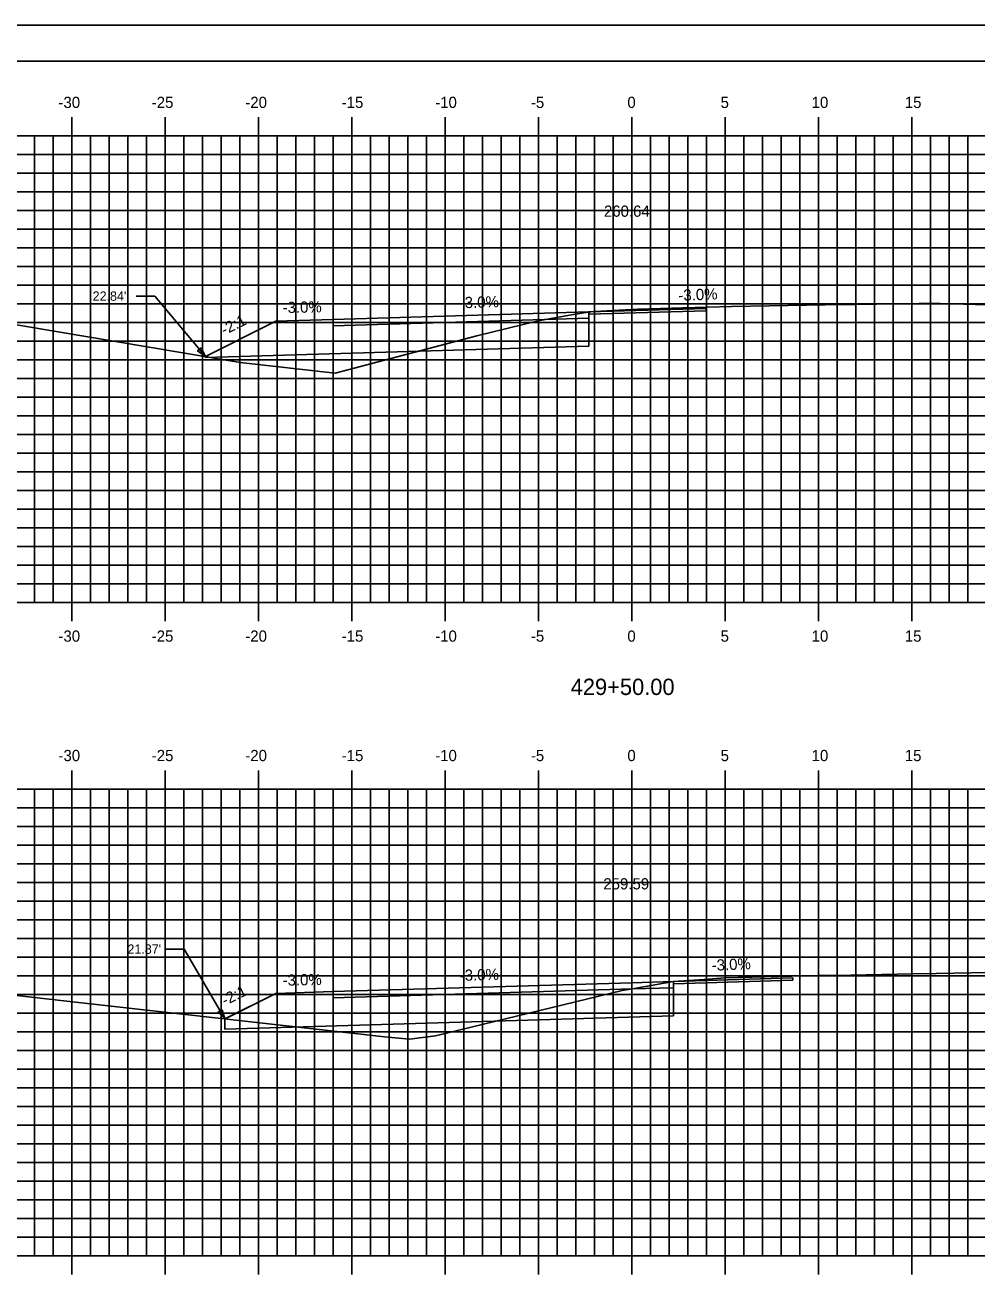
# Model space of a CAD drawing. Extents: x 1160718 to 1173142, y 616002 to 617630.
# Drawn here: x 1171038.7 to 1171089.7, y 616656.7 to 616723.9 of the extents above; entities that cross this region are included whole.
import ezdxf

# ---------------------------------------------------------------- set-up
doc = ezdxf.new("R2010")
doc.units = 0
for name, color, linetype in [('ANNOTATION', 7, 'Continuous'), ('BORDER', 7, 'Continuous'), ('D_Roadway_Centerline', 7, 'Continuous'), ('D_Roadway_Centerline_Text', 7, 'Continuous'), ('D_Roadway_Edge_Shoulder', 7, 'Continuous'), ('D_Roadway_Edge_TW', 7, 'Continuous'), ('D_Roadway_Pavement', 7, 'Continuous'), ('D_Roadway_SlopeLines', 7, 'Continuous'), ('D_Roadway_SubGrade', 7, 'Continuous'), ('H_V ANNOTATION', 7, 'Continuous'), ('MAJOR', 7, 'Continuous'), ('MINOR', 7, 'Continuous'), ('PLOT BOUNDARY', 7, 'Continuous'), ('S_Roadway_Centerline', 7, 'Continuous'), ('SHADING', 7, 'Continuous')]:
    doc.layers.add(name, color=color, linetype=linetype)

msp = doc.modelspace()

# ---------------------------------------------------------------- linework, layer by layer
at = {"layer": 'ANNOTATION'}
for p, q in [((1171044.62, 616709.347), (1171045.62, 616709.347)), ((1171048.335, 616706.106), (1171045.62, 616709.347)), ((1171068.87, 616708.499), (1171075.152, 616708.688)), ((1171068.87, 616708.374), (1171075.152, 616708.563)), ((1171075.152, 616708.688), (1171075.152, 616708.563)), ((1171055.177, 616708.087), (1171052.113, 616707.995)), ((1171046.202, 616674.353), (1171047.202, 616674.353)), ((1171049.37, 616670.612), (1171047.202, 616674.353)), ((1171073.401, 616672.622), (1171079.805, 616672.814)), ((1171079.805, 616672.814), (1171079.805, 616672.689)), ((1171055.177, 616672.075), (1171052.113, 616671.983)), ((1171073.401, 616672.497), (1171079.805, 616672.689))]:
    msp.add_line(p, q, dxfattribs=at)
for points in [[(1171048.11, 616706.57), (1171048.335, 616706.106), (1171047.918, 616706.409)], [(1171049.227, 616671.107), (1171049.37, 616670.612), (1171049.011, 616670.981)]]:
    msp.add_lwpolyline(points, close=True, dxfattribs=at)
at = {"layer": 'BORDER'}
msp.add_line((1171156.177, 616721.928), (1170996.177, 616721.928), dxfattribs=at)
at = {"layer": 'D_Roadway_Centerline'}
for points in [[(1171055.177, 616672.075), (1171071.177, 616672.555), (1171073.401, 616672.622)], [(1171049.421, 616670.637), (1171052.113, 616671.983)]]:
    msp.add_lwpolyline(points, dxfattribs=at)
at = {"layer": 'D_Roadway_Edge_Shoulder'}
for points in [[(1171055.177, 616708.087), (1171055.177, 616707.754)], [(1171055.177, 616672.043), (1171055.177, 616671.71)]]:
    msp.add_lwpolyline(points, dxfattribs=at)
at = {"layer": 'D_Roadway_Edge_TW'}
for points in [[(1171068.875, 616708.165), (1171068.875, 616708.499), (1171068.875, 616708.499), (1171055.177, 616708.087), (1171055.177, 616707.754), (1171068.875, 616708.165)], [(1171073.401, 616672.288), (1171073.401, 616672.622), (1171071.177, 616672.555), (1171055.177, 616672.075), (1171055.177, 616671.742), (1171071.177, 616672.222)]]:
    msp.add_lwpolyline(points, close=True, dxfattribs=at)
at = {"layer": 'D_Roadway_Pavement'}
for points in [[(1171068.875, 616708.165), (1171068.875, 616708.165), (1171068.875, 616708.165), (1171055.177, 616707.754), (1171055.177, 616707.754), (1171068.875, 616708.165)], [(1171071.177, 616672.222), (1171055.177, 616671.742), (1171055.177, 616671.742), (1171071.177, 616672.222)]]:
    msp.add_lwpolyline(points, close=True, dxfattribs=at)
for points in [[(1171055.177, 616707.754), (1171055.177, 616707.754)], [(1171055.177, 616707.754), (1171055.177, 616707.754)], [(1171055.177, 616671.71), (1171055.177, 616671.71)], [(1171055.177, 616671.71), (1171055.177, 616671.71)]]:
    msp.add_lwpolyline(points, dxfattribs=at)
at = {"layer": 'D_Roadway_SlopeLines'}
for points in [[(1171052.113, 616707.995), (1171048.335, 616706.106)], [(1171052.113, 616671.983), (1171049.421, 616670.637)]]:
    msp.add_lwpolyline(points, dxfattribs=at)
at = {"layer": 'D_Roadway_SubGrade'}
for p, q in [((1171052.113, 616707.995), (1171048.335, 616706.106)), ((1171068.875, 616708.165), (1171055.177, 616707.754)), ((1171055.177, 616706.254), (1171055.177, 616708.087)), ((1171055.177, 616707.754), (1171055.177, 616706.254)), ((1171068.875, 616706.665), (1171068.875, 616708.165)), ((1171068.875, 616708.165), (1171068.875, 616708.165)), ((1171048.335, 616706.106), (1171048.335, 616706.049)), ((1171071.177, 616672.222), (1171055.177, 616671.742)), ((1171055.177, 616670.242), (1171055.177, 616672.075)), ((1171073.401, 616672.288), (1171071.177, 616672.222)), ((1171073.401, 616670.788), (1171073.401, 616672.288)), ((1171052.113, 616671.983), (1171049.37, 616670.612)), ((1171055.177, 616671.742), (1171055.177, 616670.242)), ((1171049.37, 616670.612), (1171049.37, 616670.068))]:
    msp.add_line(p, q, dxfattribs=at)
at = {"layer": 'MAJOR'}
for p, q in [((1171041.177, 616718.93), (1171041.177, 616717.928)), ((1171046.177, 616718.93), (1171046.177, 616717.928)), ((1171051.177, 616718.93), (1171051.177, 616717.928)), ((1171056.177, 616718.93), (1171056.177, 616717.928)), ((1171061.177, 616718.93), (1171061.177, 616717.928)), ((1171066.177, 616718.93), (1171066.177, 616717.928)), ((1171071.177, 616718.93), (1171071.177, 616717.928)), ((1171076.177, 616718.93), (1171076.177, 616717.928)), ((1171081.177, 616718.93), (1171081.177, 616717.928)), ((1171086.177, 616718.93), (1171086.177, 616717.928)), ((1171001.177, 616717.928), (1171141.177, 616717.928)), ((1171001.177, 616717.928), (1171141.177, 616717.928)), ((1171041.177, 616692.928), (1171041.177, 616717.928)), ((1171046.177, 616692.928), (1171046.177, 616717.928)), ((1171051.177, 616692.928), (1171051.177, 616717.928)), ((1171056.177, 616692.928), (1171056.177, 616717.928)), ((1171061.177, 616692.928), (1171061.177, 616717.928)), ((1171066.177, 616692.928), (1171066.177, 616717.928)), ((1171071.177, 616692.928), (1171071.177, 616717.928)), ((1171076.177, 616692.928), (1171076.177, 616717.928)), ((1171081.177, 616692.928), (1171081.177, 616717.928)), ((1171086.177, 616692.928), (1171086.177, 616717.928)), ((1171001.177, 616712.928), (1171141.177, 616712.928)), ((1171001.177, 616707.928), (1171141.177, 616707.928)), ((1171001.177, 616702.928), (1171141.177, 616702.928)), ((1171001.177, 616697.928), (1171141.177, 616697.928)), ((1171001.177, 616692.928), (1171141.177, 616692.928)), ((1171001.177, 616692.928), (1171141.177, 616692.928)), ((1171041.177, 616691.926), (1171041.177, 616692.928)), ((1171046.177, 616691.926), (1171046.177, 616692.928)), ((1171051.177, 616691.926), (1171051.177, 616692.928)), ((1171056.177, 616691.926), (1171056.177, 616692.928)), ((1171061.177, 616691.926), (1171061.177, 616692.928)), ((1171066.177, 616691.926), (1171066.177, 616692.928)), ((1171071.177, 616691.926), (1171071.177, 616692.928)), ((1171076.177, 616691.926), (1171076.177, 616692.928)), ((1171081.177, 616691.926), (1171081.177, 616692.928)), ((1171086.177, 616691.926), (1171086.177, 616692.928)), ((1171041.177, 616683.93), (1171041.177, 616682.928)), ((1171046.177, 616683.93), (1171046.177, 616682.928)), ((1171051.177, 616683.93), (1171051.177, 616682.928)), ((1171056.177, 616683.93), (1171056.177, 616682.928)), ((1171061.177, 616683.93), (1171061.177, 616682.928)), ((1171066.177, 616683.93), (1171066.177, 616682.928)), ((1171071.177, 616683.93), (1171071.177, 616682.928)), ((1171076.177, 616683.93), (1171076.177, 616682.928)), ((1171081.177, 616683.93), (1171081.177, 616682.928)), ((1171086.177, 616683.93), (1171086.177, 616682.928)), ((1171001.177, 616682.928), (1171141.177, 616682.928)), ((1171001.177, 616682.928), (1171141.177, 616682.928)), ((1171041.177, 616657.928), (1171041.177, 616682.928)), ((1171046.177, 616657.928), (1171046.177, 616682.928)), ((1171051.177, 616657.928), (1171051.177, 616682.928)), ((1171056.177, 616657.928), (1171056.177, 616682.928)), ((1171061.177, 616657.928), (1171061.177, 616682.928)), ((1171066.177, 616657.928), (1171066.177, 616682.928)), ((1171071.177, 616657.928), (1171071.177, 616682.928)), ((1171076.177, 616657.928), (1171076.177, 616682.928)), ((1171081.177, 616657.928), (1171081.177, 616682.928)), ((1171086.177, 616657.928), (1171086.177, 616682.928)), ((1171001.177, 616677.928), (1171141.177, 616677.928)), ((1171001.177, 616672.928), (1171141.177, 616672.928)), ((1171001.177, 616667.928), (1171141.177, 616667.928)), ((1171001.177, 616662.928), (1171141.177, 616662.928)), ((1171001.177, 616657.928), (1171141.177, 616657.928)), ((1171001.177, 616657.928), (1171141.177, 616657.928)), ((1171041.177, 616656.926), (1171041.177, 616657.928)), ((1171046.177, 616656.926), (1171046.177, 616657.928)), ((1171051.177, 616656.926), (1171051.177, 616657.928)), ((1171056.177, 616656.926), (1171056.177, 616657.928)), ((1171061.177, 616656.926), (1171061.177, 616657.928)), ((1171066.177, 616656.926), (1171066.177, 616657.928)), ((1171071.177, 616656.926), (1171071.177, 616657.928)), ((1171076.177, 616656.926), (1171076.177, 616657.928)), ((1171081.177, 616656.926), (1171081.177, 616657.928)), ((1171086.177, 616656.926), (1171086.177, 616657.928))]:
    msp.add_line(p, q, dxfattribs=at)
at = {"layer": 'MINOR'}
for p, q in [((1171039.177, 616692.928), (1171039.177, 616717.928)), ((1171040.177, 616692.928), (1171040.177, 616717.928)), ((1171042.177, 616692.928), (1171042.177, 616717.928)), ((1171043.177, 616692.928), (1171043.177, 616717.928)), ((1171044.177, 616692.928), (1171044.177, 616717.928)), ((1171045.177, 616692.928), (1171045.177, 616717.928)), ((1171047.177, 616692.928), (1171047.177, 616717.928)), ((1171048.177, 616692.928), (1171048.177, 616717.928)), ((1171049.177, 616692.928), (1171049.177, 616717.928)), ((1171050.177, 616692.928), (1171050.177, 616717.928)), ((1171052.177, 616692.928), (1171052.177, 616717.928)), ((1171053.177, 616692.928), (1171053.177, 616717.928)), ((1171054.177, 616692.928), (1171054.177, 616717.928)), ((1171055.177, 616692.928), (1171055.177, 616717.928)), ((1171057.177, 616692.928), (1171057.177, 616717.928)), ((1171058.177, 616692.928), (1171058.177, 616717.928)), ((1171059.177, 616692.928), (1171059.177, 616717.928)), ((1171060.177, 616692.928), (1171060.177, 616717.928)), ((1171062.177, 616692.928), (1171062.177, 616717.928)), ((1171063.177, 616692.928), (1171063.177, 616717.928)), ((1171064.177, 616692.928), (1171064.177, 616717.928)), ((1171065.177, 616692.928), (1171065.177, 616717.928)), ((1171067.177, 616692.928), (1171067.177, 616717.928)), ((1171068.177, 616692.928), (1171068.177, 616717.928)), ((1171069.177, 616692.928), (1171069.177, 616717.928)), ((1171070.177, 616692.928), (1171070.177, 616717.928)), ((1171072.177, 616692.928), (1171072.177, 616717.928)), ((1171073.177, 616692.928), (1171073.177, 616717.928)), ((1171074.177, 616692.928), (1171074.177, 616717.928)), ((1171075.177, 616692.928), (1171075.177, 616717.928)), ((1171077.177, 616692.928), (1171077.177, 616717.928)), ((1171078.177, 616692.928), (1171078.177, 616717.928)), ((1171079.177, 616692.928), (1171079.177, 616717.928)), ((1171080.177, 616692.928), (1171080.177, 616717.928)), ((1171082.177, 616692.928), (1171082.177, 616717.928)), ((1171083.177, 616692.928), (1171083.177, 616717.928)), ((1171084.177, 616692.928), (1171084.177, 616717.928)), ((1171085.177, 616692.928), (1171085.177, 616717.928)), ((1171087.177, 616692.928), (1171087.177, 616717.928)), ((1171088.177, 616692.928), (1171088.177, 616717.928)), ((1171089.177, 616692.928), (1171089.177, 616717.928)), ((1171001.177, 616716.928), (1171141.177, 616716.928)), ((1171001.177, 616715.928), (1171141.177, 616715.928)), ((1171001.177, 616714.928), (1171141.177, 616714.928)), ((1171001.177, 616713.928), (1171141.177, 616713.928)), ((1171001.177, 616711.928), (1171141.177, 616711.928)), ((1171001.177, 616710.928), (1171141.177, 616710.928)), ((1171001.177, 616709.928), (1171141.177, 616709.928)), ((1171001.177, 616708.928), (1171141.177, 616708.928)), ((1171001.177, 616706.928), (1171141.177, 616706.928)), ((1171001.177, 616705.928), (1171141.177, 616705.928)), ((1171001.177, 616704.928), (1171141.177, 616704.928)), ((1171001.177, 616703.928), (1171141.177, 616703.928)), ((1171001.177, 616701.928), (1171141.177, 616701.928)), ((1171001.177, 616700.928), (1171141.177, 616700.928)), ((1171001.177, 616699.928), (1171141.177, 616699.928)), ((1171001.177, 616698.928), (1171141.177, 616698.928)), ((1171001.177, 616696.928), (1171141.177, 616696.928)), ((1171001.177, 616695.928), (1171141.177, 616695.928)), ((1171001.177, 616694.928), (1171141.177, 616694.928)), ((1171001.177, 616693.928), (1171141.177, 616693.928)), ((1171039.177, 616657.928), (1171039.177, 616682.928)), ((1171040.177, 616657.928), (1171040.177, 616682.928)), ((1171042.177, 616657.928), (1171042.177, 616682.928)), ((1171043.177, 616657.928), (1171043.177, 616682.928)), ((1171044.177, 616657.928), (1171044.177, 616682.928)), ((1171045.177, 616657.928), (1171045.177, 616682.928)), ((1171047.177, 616657.928), (1171047.177, 616682.928)), ((1171048.177, 616657.928), (1171048.177, 616682.928)), ((1171049.177, 616657.928), (1171049.177, 616682.928)), ((1171050.177, 616657.928), (1171050.177, 616682.928)), ((1171052.177, 616657.928), (1171052.177, 616682.928)), ((1171053.177, 616657.928), (1171053.177, 616682.928)), ((1171054.177, 616657.928), (1171054.177, 616682.928)), ((1171055.177, 616657.928), (1171055.177, 616682.928)), ((1171057.177, 616657.928), (1171057.177, 616682.928)), ((1171058.177, 616657.928), (1171058.177, 616682.928)), ((1171059.177, 616657.928), (1171059.177, 616682.928)), ((1171060.177, 616657.928), (1171060.177, 616682.928)), ((1171062.177, 616657.928), (1171062.177, 616682.928)), ((1171063.177, 616657.928), (1171063.177, 616682.928)), ((1171064.177, 616657.928), (1171064.177, 616682.928)), ((1171065.177, 616657.928), (1171065.177, 616682.928)), ((1171067.177, 616657.928), (1171067.177, 616682.928)), ((1171068.177, 616657.928), (1171068.177, 616682.928)), ((1171069.177, 616657.928), (1171069.177, 616682.928)), ((1171070.177, 616657.928), (1171070.177, 616682.928)), ((1171072.177, 616657.928), (1171072.177, 616682.928)), ((1171073.177, 616657.928), (1171073.177, 616682.928)), ((1171074.177, 616657.928), (1171074.177, 616682.928)), ((1171075.177, 616657.928), (1171075.177, 616682.928)), ((1171077.177, 616657.928), (1171077.177, 616682.928)), ((1171078.177, 616657.928), (1171078.177, 616682.928)), ((1171079.177, 616657.928), (1171079.177, 616682.928)), ((1171080.177, 616657.928), (1171080.177, 616682.928)), ((1171082.177, 616657.928), (1171082.177, 616682.928)), ((1171083.177, 616657.928), (1171083.177, 616682.928)), ((1171084.177, 616657.928), (1171084.177, 616682.928)), ((1171085.177, 616657.928), (1171085.177, 616682.928)), ((1171087.177, 616657.928), (1171087.177, 616682.928)), ((1171088.177, 616657.928), (1171088.177, 616682.928)), ((1171089.177, 616657.928), (1171089.177, 616682.928)), ((1171001.177, 616681.928), (1171141.177, 616681.928)), ((1171001.177, 616680.928), (1171141.177, 616680.928)), ((1171001.177, 616679.928), (1171141.177, 616679.928)), ((1171001.177, 616678.928), (1171141.177, 616678.928)), ((1171001.177, 616676.928), (1171141.177, 616676.928)), ((1171001.177, 616675.928), (1171141.177, 616675.928)), ((1171001.177, 616674.928), (1171141.177, 616674.928)), ((1171001.177, 616673.928), (1171141.177, 616673.928)), ((1171001.177, 616671.928), (1171141.177, 616671.928)), ((1171001.177, 616670.928), (1171141.177, 616670.928)), ((1171001.177, 616669.928), (1171141.177, 616669.928)), ((1171001.177, 616668.928), (1171141.177, 616668.928)), ((1171001.177, 616666.928), (1171141.177, 616666.928)), ((1171001.177, 616665.928), (1171141.177, 616665.928)), ((1171001.177, 616664.928), (1171141.177, 616664.928)), ((1171001.177, 616663.928), (1171141.177, 616663.928)), ((1171001.177, 616661.928), (1171141.177, 616661.928)), ((1171001.177, 616660.928), (1171141.177, 616660.928)), ((1171001.177, 616659.928), (1171141.177, 616659.928)), ((1171001.177, 616658.928), (1171141.177, 616658.928))]:
    msp.add_line(p, q, dxfattribs=at)
at = {"layer": 'PLOT BOUNDARY'}
msp.add_lwpolyline([(1170988.084, 616613.869), (1171158.084, 616613.869), (1171158.084, 616723.869), (1170988.084, 616723.869)], close=True, dxfattribs=at)
at = {"layer": 'S_Roadway_Centerline'}
for points in [[(1171001.177, 616711.386), (1171002.774, 616711.305), (1171027.844, 616709.22), (1171033.751, 616708.551), (1171050.193, 616705.795), (1171055.292, 616705.219), (1171062.868, 616707.222), (1171066.159, 616708.021), (1171067.935, 616708.335), (1171068.833, 616708.493), (1171068.875, 616708.499), (1171068.98, 616708.506), (1171069.175, 616708.516), (1171071.491, 616708.644), (1171073.911, 616708.712), (1171076.51, 616708.782), (1171078.529, 616708.819), (1171081.529, 616708.875), (1171083.147, 616708.899), (1171086.548, 616708.95), (1171087.381, 616708.947), (1171087.685, 616708.946), (1171090.852, 616708.865)], [(1171001.177, 616675.089), (1171015.071, 616674.377), (1171018.68, 616674.081), (1171041.705, 616671.472), (1171057.919, 616669.652), (1171059.27, 616669.526), (1171060.664, 616669.715), (1171070.66, 616672.135), (1171071.209, 616672.226), (1171071.706, 616672.316), (1171073.401, 616672.622), (1171075.053, 616672.734), (1171076.158, 616672.809), (1171078.323, 616672.862), (1171081.183, 616672.933), (1171082.895, 616672.966), (1171086.207, 616673.029), (1171087.467, 616673.05), (1171091.232, 616673.113)]]:
    msp.add_lwpolyline(points, dxfattribs=at)
at = {"layer": 'SHADING'}
for p, q in [((1171048.335, 616706.049), (1171068.875, 616706.665)), ((1171049.37, 616670.068), (1171073.401, 616670.788))]:
    msp.add_line(p, q, dxfattribs=at)

# ---------------------------------------------------------------- texts
at = {"layer": 'ANNOTATION'}
for s, rotation, p in [('-3.0%', 2.26142, (1171073.677, 616709.088)), ('-3.0%', 1.14576, (1171052.474, 616708.434)), ('-3.0%', 1.71836, (1171061.965, 616708.691)), ('-2:1', 26.56505, (1171049.351, 616707.236)), ('-3.0%', 2.4823, (1171075.462, 616673.19)), ('-3.0%', 1.14576, (1171052.474, 616672.39)), ('-3.0%', 1.71836, (1171061.965, 616672.648)), ('-2:1', 26.56505, (1171049.379, 616671.304))]:
    msp.add_text(s, height=0.6, rotation=rotation, dxfattribs=at).set_placement(p)
for s, p in [("22.84'", (1171042.295, 616709.097)), ("21.87'", (1171044.158, 616674.103))]:
    msp.add_text(s, height=0.5, dxfattribs=at).set_placement(p)
at = {"layer": 'D_Roadway_Centerline'}
for s, p in [('C', (1171071.171, 616708.567)), ('L', (1171071.177, 616708.56)), ('C', (1171071.171, 616672.523)), ('L', (1171071.177, 616672.516))]:
    msp.add_text(s, height=0.0146, dxfattribs=at).set_placement(p)
at = {"layer": 'D_Roadway_Centerline_Text'}
for s, p in [('260.64', (1171069.678, 616713.599)), ('259.59', (1171069.646, 616677.555))]:
    msp.add_text(s, height=0.6, dxfattribs=at).set_placement(p)
at = {"layer": 'H_V ANNOTATION'}
for s, height, p in [('-30', 0.6, (1171040.465, 616719.428)), ('-25', 0.6, (1171045.462, 616719.428)), ('-20', 0.6, (1171050.47, 616719.428)), ('-15', 0.6, (1171055.634, 616719.428)), ('-10', 0.6, (1171060.642, 616719.428)), ('-5', 0.6, (1171065.767, 616719.428)), ('0', 0.6, (1171070.936, 616719.428)), ('5', 0.6, (1171075.928, 616719.428)), ('10', 0.6, (1171080.802, 616719.428)), ('15', 0.6, (1171085.794, 616719.428)), ('-30', 0.6, (1171040.465, 616690.828)), ('-25', 0.6, (1171045.462, 616690.828)), ('-20', 0.6, (1171050.47, 616690.828)), ('-15', 0.6, (1171055.634, 616690.828)), ('-10', 0.6, (1171060.642, 616690.828)), ('-5', 0.6, (1171065.767, 616690.828)), ('0', 0.6, (1171070.936, 616690.828)), ('5', 0.6, (1171075.928, 616690.828)), ('10', 0.6, (1171080.802, 616690.828)), ('15', 0.6, (1171085.794, 616690.828)), ('429+50.00', 0.875, (1171067.899, 616687.971)), ('-30', 0.6, (1171040.465, 616684.428)), ('-25', 0.6, (1171045.462, 616684.428)), ('-20', 0.6, (1171050.47, 616684.428)), ('-15', 0.6, (1171055.634, 616684.428)), ('-10', 0.6, (1171060.642, 616684.428)), ('-5', 0.6, (1171065.767, 616684.428)), ('0', 0.6, (1171070.936, 616684.428)), ('5', 0.6, (1171075.928, 616684.428)), ('10', 0.6, (1171080.802, 616684.428)), ('15', 0.6, (1171085.794, 616684.428))]:
    msp.add_text(s, height=height, dxfattribs=at).set_placement(p)

doc.saveas('drawing.dxf')
